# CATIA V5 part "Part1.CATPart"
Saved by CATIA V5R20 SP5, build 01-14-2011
Part number: 瓶子
Material "Bathroom Floor": density 2770 kg/m3, Young's modulus 6e+10 Pa, Poisson ratio 0.3
Bounding box of the stored display mesh (mm): x -25 to 25, y -25 to 25, z 0 to 90
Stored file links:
  E:\瓶子\Part1.CATPart
  C:\Program Files\Dassault Systemes\B20\intel_a\startup\materials\Catalog.CATMaterial
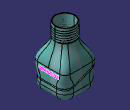
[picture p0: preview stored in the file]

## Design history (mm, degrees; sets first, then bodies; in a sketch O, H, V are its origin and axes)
Set1
  Sketch1 on xy-plane, origin (0, 0, 0), H (1, 0, 0), V (0, 1, 0)
    line L1 (25, 25) -> (25, -25)
    line L2 (25, -25) -> (-25, -25)
    line L3 (-25, -25) -> (-25, 25)
    line L4 (-25, 25) -> (25, 25)
    length L4 = 50
    length L1 = 50
    vertical: L1 V, L3 V
    horizontal: L2 H, L4 H
    equidistance: L1 L3 O, L2 L4 O
  Sketch2 on face of Pad1 from Sketch1.L2, origin (0, -25, 0), H (1, 0, 0), V (0, 0, 1)
    spline S1 through (-60, 20) (-15.0525, 31.397) (12.6433, 20.9001) (50, 30)
  Extrude1: Element1 Sketch2, Lim1 50, Lim2 0, Direction face of Pad1 from Sketch1.L2
  MultiSel1: CommonCtxFeats ({extract ExtractElem face of Pad1 from Sketch1.L2}; {extract ExtractElem face of Fillet1}; {extract ExtractElem face of Pad1 from Sketch1.L1}; {extract ExtractElem face of Fillet1}; {extract ExtractElem face of Pad1 from Sketch1.L4}; {extract ExtractElem face of Fillet1}; {extract ExtractElem face of Pad1 from Sketch1.L3}; {extract ExtractElem face of Fillet1})
  Join1: Elements ({intersect ToIntersect1 {extract ExtractElem face of Pad1 from Sketch1.L2}, ToIntersect2 Extrude1}; {intersect ToIntersect1 {extract ExtractElem face of Fillet1}, ToIntersect2 Extrude1}; {intersect ToIntersect1 {extract ExtractElem face of Pad1 from Sketch1.L1}, ToIntersect2 Extrude1}; {intersect ToIntersect1 {extract ExtractElem face of Fillet1}, ToIntersect2 Extrude1}; {intersect ToIntersect1 {extract ExtractElem face of Pad1 from Sketch1.L4}, ToIntersect2 Extrude1}; {intersect ToIntersect1 {extract ExtractElem face of Fillet1}, ToIntersect2 Extrude1}; {intersect ToIntersect1 {extract ExtractElem face of Pad1 from Sketch1.L3}, ToIntersect2 Extrude1}; {intersect ToIntersect1 {extract ExtractElem face of Fillet1}, ToIntersect2 Extrude1})
  Plane1: type Normal, Curve Join1, RefPoint vertex [face of MultiSel1 | face of MultiSel1]
  Sketch3 on Plane1, origin (5.8902, 0, -1.5889), H (0, -1, 0), V (0.2604, 0, 0.9655)
    circle A1 centre (-25.2722, 23.5044) radius 1
    radius A1 = 1
Body1 (main body)
  Pad1: profile Sketch1, direction (0, 0, 1), length 40
  Fillet1: on edge [face of Pad1 from Sketch1.L4 | face of Pad1 from Sketch1.L1]; edge [face of Pad1 from Sketch1.L3 | face of Pad1 from Sketch1.L4]; edge [face of Pad1 from Sketch1.L1 | face of Pad1 from Sketch1.L2]; edge [face of Pad1 from Sketch1.L2 | face of Pad1 from Sketch1.L3]
  Fillet2: radius 13, on edge [start face of Pad1 | face of Fillet1]
  Plane2: type Offset, RefPlane end face of Pad1, Offset 50, reversed
  Sketch4 on Plane2, origin (0, 0, 90), H (1, 0, 0), V (0, -1, 0)
    circle A1 centre (0, 0) radius 15
    radius A1 = 15
  Pad2: profile Sketch4, direction (0, 0, -1), length 20
  Sketch5 on end face of Pad1, origin (0, 0, 40), H (1, 0, 0), V (0, 1, 0)
    point P1 (25, 0)
    distance P1 O = 25
  Sketch6 on end face of Pad2, origin (0, 0, 70), H (1, 0, 0), V (0, -1, 0)
    point P1 (15, 0)
    distance P1 O = 15
    coincidence: P1 H
  Loft1: solid, Sections ({boundary Boundary {extract ExtractElem end face of Pad2}}; {boundary Boundary {extract ExtractElem end face of Pad1}}), StartFace end face of Pad2, EndFace end face of Pad1
  Slot1: profile Sketch3, centre curve Join1
  Shell1: ExtOffset 0, Face start face of Pad2, IntOffset 1
  Sketch7 on face of Pad1 from Sketch1.L4, origin (0, 25, 0), H (-1, 0, 0), V (0, 0, 1)
    spline S1 through (-30.3712, 16.4366) (-11.7896, 14.2473) (34.3264, 31.2565) (43.6171, 31.2565)
  Extrude2: Lim1 50, Lim2 50, Element1 Sketch7
  Plane3: type Offset, RefPlane xy-plane, Offset 71
Body2
  Sketch8 on face of Pad1 from Sketch1.L3, origin (-25, 0, 0), H (0, -1, 0), V (0, 0, 1)
    polyline C1
    polyline C2
    polyline C3
    polyline C4
    polyline C5
    polyline C6
    polyline C7
    polyline C8
    polyline C9
    polyline C10
    polyline C11
  Pad3: profile Sketch8, direction (1, 0, 0), length 0.5
  Fillet3: on edge [face of Pad3 from Sketch8.C10 | start face of Pad3], deactivated
  Sketch9 on Plane3, origin (0, 0, 71), H (1, 0, 0), V (0, 1, 0)
    point P1 (15, 0)
    distance P1 O = 15
    coincidence: P1 H
  Helix1: Direction Z axis, RefPoint Sketch9, Pitch 3, Height 16, TaperAngle 0
  Point1: type OnCurve, Support Helix1, RefPoint Sketch9, Length 7.163
  Point2: type OnCurve, Support Helix1, Length 6.878
  Line1: type PtDir, RefPoint Sketch9, Direction (1, 0, 0), Support {extract ExtractElem end face of Pad2}, Start 0, End 8
  Connect1: Curve1 Line1, Point1 vertex of Line1, Tension1 1, Curve2 Helix1, Point2 Point1, Tension2 1
  Line2: type PtDir, RefPoint vertex of Helix1, Direction (0, 1, 0), Start 0, End 10
  Connect2: Curve1 Line2, Point1 vertex of Line2, Tension1 2.8, Curve2 Helix1, Point2 Point2, Tension2 1
  Plane4: type Normal, Curve Connect1, RefPoint Point1
  Sketch10 on Plane4, origin (-1.0405, 2.0118, 0.0721), H (-0.8882, -0.4594, 0), V (0.0146, -0.0283, 0.9995)
    circle A1 centre (-14.9074, 71.0271) radius 0.5198
  Rib1: profile Sketch10, centre curve Connect1
  Sketch11 on face of Pad1 from Sketch1.L1, origin (25, 0, 0), H (0, 1, 0), V (0, 0, 1)
    polyline C1
    polyline C2
    polyline C3
    polyline C4
    polyline C5
    polyline C6
    polyline C7
    polyline C8
    polyline C9
    polyline C10
    polyline C11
